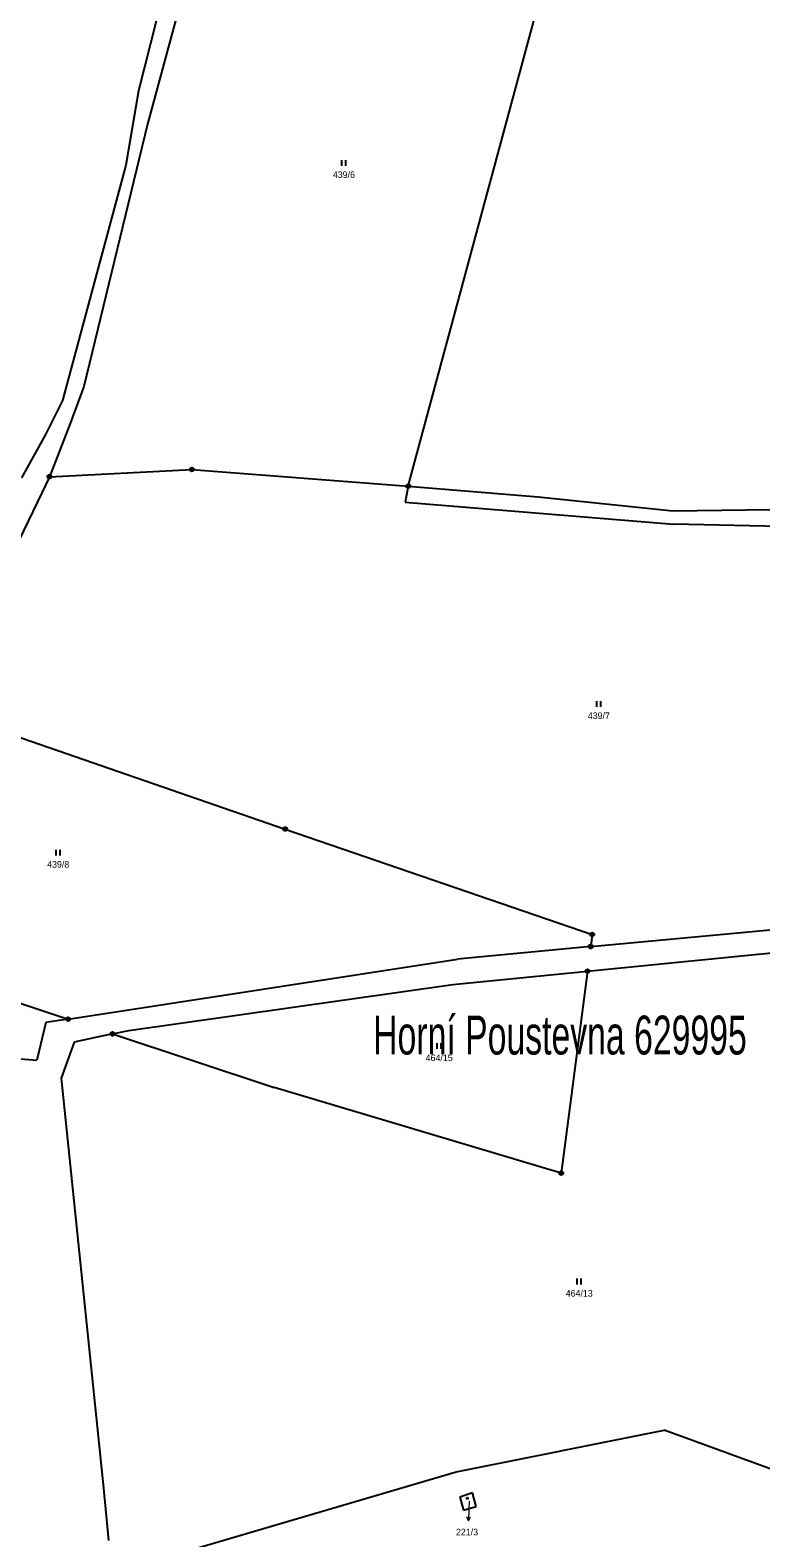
# Model space of a CAD drawing. Extents: x -739410 to -735662, y -942282 to -940043.
# Drawn here: x -737384.4 to -737196.3, y -941581.8 to -941193.9 of the extents above; entities that cross this region are included whole.
import ezdxf
from ezdxf.enums import TextEntityAlignment as Align

# ---------------------------------------------------------------- set-up
doc = ezdxf.new("R2010")
doc.units = 0
doc.header["$LTSCALE"] = 0.68
for name, color, linetype, lineweight in [('1', 7, 'Continuous', 25), ('3', 7, 'Continuous', 25), ('5', 7, 'Continuous', 25), ('7', 7, 'Continuous', 13), ('8', 7, 'Continuous', 25)]:
    doc.layers.add(name, color=color, linetype=linetype, lineweight=lineweight)
doc.layers.add('2', color=7, linetype='Continuous')

msp = doc.modelspace()

# ---------------------------------------------------------------- linework, layer by layer
at = {"layer": '1'}
for p, q in [((-737332.96, -941139.48), (-737354.17, -941218.16)), ((-737342.51, -941154.16), (-737356.53, -941209.52)), ((-737287.08, -941311.26), (-737244.75, -941154.46)), ((-737356.53, -941209.52), (-737359.75, -941228.69)), ((-737354.17, -941218.16), (-737370.55, -941285.59)), ((-737359.75, -941228.69), (-737376.07, -941289.26)), ((-737370.55, -941285.59), (-737374.09, -941295.16)), ((-737376.07, -941289.26), (-737380.49, -941297.99)), ((-737380.49, -941297.99), (-737386.64, -941309.11)), ((-737374.09, -941295.16), (-737379.44, -941308.83)), ((-737379.44, -941308.83), (-737381.43, -941312.98)), ((-737379.44, -941308.83), (-737342.77, -941306.97)), ((-737342.77, -941306.97), (-737287.08, -941311.26)), ((-737381.43, -941312.98), (-737402.36, -941356.33)), ((-737287.08, -941311.26), (-737287.92, -941315.38)), ((-737287.08, -941311.26), (-737253.63, -941314)), ((-737253.63, -941314), (-737219, -941317.58)), ((-737287.92, -941315.38), (-737218.79, -941321.04)), ((-737219, -941317.58), (-737134.81, -941316.59)), ((-737155.06, -941322.53), (-737218.79, -941321.04)), ((-737408.16, -941368.6), (-737318.79, -941399.47)), ((-737318.79, -941399.47), (-737239.74, -941426.61)), ((-737240.96, -941436.04), (-737146.41, -941426.71)), ((-737240.14, -941429.73), (-737176.05, -941423.74)), ((-737239.74, -941426.61), (-737240.14, -941429.73)), ((-737436.99, -941427.7), (-737374.65, -941448.39)), ((-737240.14, -941429.73), (-737274.45, -941432.94)), ((-737374.65, -941448.39), (-737274.45, -941432.94)), ((-737275.61, -941439.46), (-737240.96, -941436.04)), ((-737240.96, -941436.04), (-737247.72, -941488)), ((-737359.02, -941451.3), (-737275.61, -941439.46)), ((-737380.33, -941449.26), (-737382.68, -941458.93)), ((-737374.65, -941448.39), (-737380.33, -941449.26)), ((-737363.2, -941452.19), (-737373.04, -941454.29)), ((-737363.2, -941452.19), (-737359.02, -941451.3)), ((-737363.2, -941452.19), (-737321.6, -941465.99)), ((-737426.13, -941455.54), (-737382.68, -941458.93)), ((-737373.04, -941454.29), (-737376.41, -941463.58)), ((-737376.41, -941463.58), (-737365.57, -941569.02)), ((-737247.72, -941488), (-737321.6, -941465.99)), ((-737274.72, -941564.87), (-737221.19, -941554.16)), ((-737188.29, -941566.13), (-737221.19, -941554.16)), ((-737349.15, -941586.68), (-737274.72, -941564.87)), ((-737365.57, -941569.02), (-737364.27, -941582.48)), ((-737270.57, -941570.29), (-737273.79, -941571.33)), ((-737269.64, -941573.73), (-737270.57, -941570.29)), ((-737273.79, -941571.33), (-737272.86, -941574.71)), ((-737272.86, -941574.71), (-737269.64, -941573.73))]:
    msp.add_line(p, q, dxfattribs=at)
at = {"layer": '3'}
for p, q in [((-737304.161, -941228.86), (-737304.161, -941227.36)), ((-737303.16, -941228.86), (-737303.16, -941227.36)), ((-737238.551, -941368.06), (-737238.551, -941366.56)), ((-737237.55, -941368.06), (-737237.55, -941366.56)), ((-737377.701, -941406.29), (-737377.701, -941404.79)), ((-737376.7, -941406.29), (-737376.7, -941404.79)), ((-737279.641, -941456.06), (-737279.641, -941454.56)), ((-737278.64, -941456.06), (-737278.64, -941454.56)), ((-737243.591, -941516.65), (-737243.591, -941515.15)), ((-737242.59, -941516.65), (-737242.59, -941515.15))]:
    msp.add_line(p, q, dxfattribs=at)
at = {"layer": '5'}
msp.add_circle((-737271.9168, -941571.6492), 0.175, dxfattribs=at)
at = {"layer": '7'}
msp.add_line((-737271.552, -941577.441), (-737271.034, -941576.448), dxfattribs=at)
msp.add_lwpolyline([(-737271.45, -941572.41), (-737271.5, -941574.44), (-737271.552, -941577.441), (-737272.036, -941576.43)], dxfattribs=at)
at = {"layer": '8'}
for centre, radius in [((-737342.77, -941306.9699), 0.5), ((-737379.44, -941308.8299), 0.5), ((-737379.44, -941308.8299), 0.0303), ((-737342.77, -941306.9699), 0.0303), ((-737287.08, -941311.2599), 0.5), ((-737287.08, -941311.2599), 0.0303), ((-737318.79, -941399.4699), 0.5), ((-737318.79, -941399.4699), 0.0303), ((-737239.74, -941426.6099), 0.5), ((-737239.74, -941426.6099), 0.0303), ((-737240.14, -941429.7299), 0.5), ((-737240.14, -941429.7299), 0.0303), ((-737240.96, -941436.0399), 0.5), ((-737240.96, -941436.0399), 0.0303), ((-737374.65, -941448.3899), 0.5), ((-737374.65, -941448.3899), 0.0303), ((-737363.2, -941452.1899), 0.5), ((-737363.2, -941452.1899), 0.0303), ((-737247.72, -941487.9999), 0.5), ((-737247.72, -941487.9999), 0.0303)]:
    msp.add_circle(centre, radius, dxfattribs=at)

# ---------------------------------------------------------------- texts
at = {"layer": '2'}
for s, p in [('439/6', (-737303.65, -941231.985)), ('439/7', (-737238.04, -941371.185)), ('439/8', (-737377.19, -941409.415)), ('464/15', (-737279.13, -941459.185)), ('464/13', (-737243.08, -941519.775))]:
    msp.add_text(s, height=1.7, dxfattribs=at).set_placement(p, align=Align.CENTER)
msp.add_text('221/3', height=1.7, dxfattribs=at).set_placement((-737269.12, -941581.185), align=Align.RIGHT)
at = {"layer": '7', "width": 0.65}
msp.add_text('Horní Poustevna 629995', height=10, dxfattribs=at).set_placement((-737248.039, -941457.483), align=Align.CENTER)

doc.saveas('drawing.dxf')
